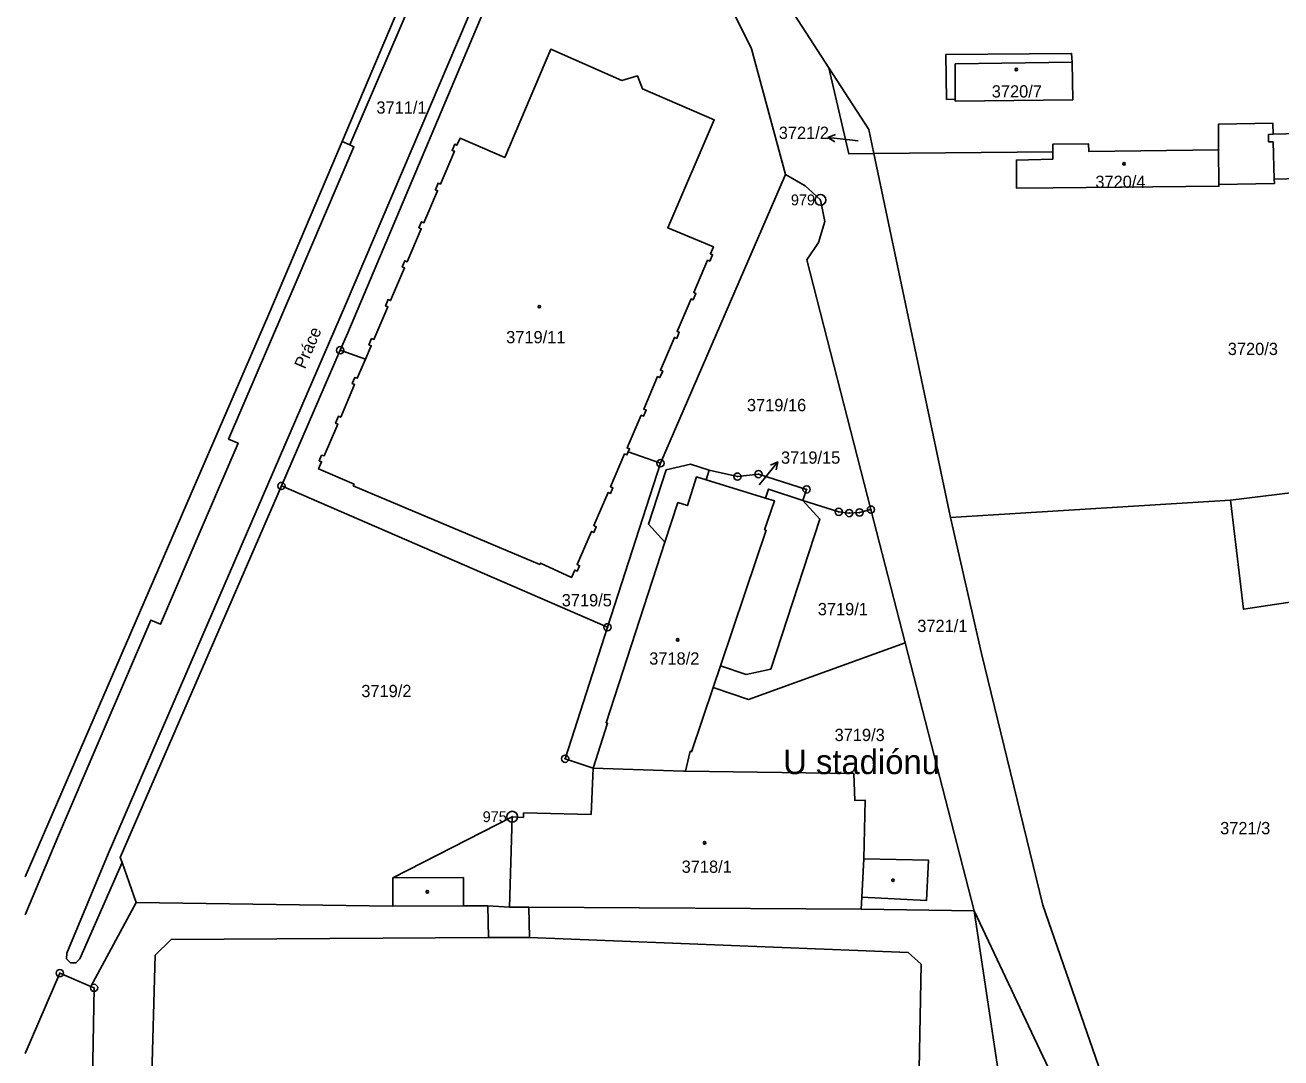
# Model space of a CAD drawing. Extents: x -747779 to -747197, y -965543 to -964919.
# Drawn here: x -747775.5 to -747601.4, y -965381 to -965237.8 of the extents above; entities that cross this region are included whole.
import ezdxf

# ---------------------------------------------------------------- set-up
doc = ezdxf.new("R2010")
doc.units = 0
for name, color, linetype in [('Hranice parcel', 7, 'Continuous'), ('Parcelní čísla', 7, 'Continuous'), ('Pop  PČ popisy', 7, 'Continuous'), ('Vnitřní kresba', 7, 'Continuous'), ('Značky bodu BP', 7, 'Continuous'), ('Značky budov', 7, 'Continuous')]:
    doc.layers.add(name, color=color, linetype=linetype)

msp = doc.modelspace()

# ---------------------------------------------------------------- linework, layer by layer
at = {"layer": 'Hranice parcel'}
for p, q in [((-747681.26, -965217.18), (-747664.09, -965243.73)), ((-747657.85, -965255.61), (-747633.05, -965255.35)), ((-747657.85, -965255.61), (-747647.24, -965306.07)), ((-747687.45, -965298.55), (-747670.12, -965258.53)), ((-747731.85, -965282.88), (-747740, -965301.7)), ((-747731.85, -965282.88), (-747728.35, -965284.12)), ((-747691.91, -965296.97), (-747687.45, -965298.55)), ((-747694.79, -965321.29), (-747687.45, -965298.55)), ((-747694.79, -965321.29), (-747740, -965301.7)), ((-747653.53, -965323.44), (-747658.27, -965304.98)), ((-747643.98, -965360.59), (-747653.53, -965323.44)), ((-747760.15, -965359.47), (-747766.44, -965371.1)), ((-747724.54, -965359.98), (-747760.15, -965359.47)), ((-747643.98, -965360.59), (-747659.62, -965360.4)), ((-747625.57, -965399.47), (-747643.98, -965360.59))]:
    msp.add_line(p, q, dxfattribs=at)
for points in [[(-747656.73, -965070.94), (-747661.79, -965091.8), (-747695.94, -965170.11), (-747711.36, -965206.23), (-747731.59, -965253.94)], [(-747687.21, -965223.29), (-747695.62, -965214.69), (-747698.17, -965212.99), (-747701.29, -965213.25), (-747703.51, -965215.83), (-747730.8, -965280.44), (-747731.85, -965282.88)], [(-747687.21, -965223.29), (-747677.55, -965235.57), (-747674.82, -965241.09), (-747670.12, -965258.53)], [(-747728.35, -965284.12), (-747727.55, -965282.25), (-747727.87, -965282.11), (-747727.5, -965281.26), (-747727.17, -965281.38), (-747725.24, -965276.87), (-747725.56, -965276.73), (-747725.2, -965275.86), (-747724.87, -965275.99), (-747722.93, -965271.46), (-747723.25, -965271.32), (-747722.89, -965270.47), (-747722.56, -965270.6), (-747720.61, -965266.04), (-747720.94, -965265.9), (-747720.58, -965265.06), (-747720.25, -965265.2), (-747718.35, -965260.75), (-747718.65, -965260.62), (-747718.28, -965259.69), (-747717.95, -965259.83), (-747716.02, -965255.29), (-747716.33, -965255.16), (-747715.97, -965254.31), (-747715.67, -965254.44), (-747715.24, -965253.48), (-747709.04, -965256.13), (-747702.67, -965241.15), (-747692.8, -965245.46), (-747690.64, -965244.84), (-747689.96, -965246.61), (-747679.99, -965250.94), (-747686.45, -965265.9), (-747680.12, -965268.53), (-747680.53, -965269.5), (-747680.22, -965269.63), (-747680.61, -965270.52), (-747680.92, -965270.39), (-747682.84, -965274.88), (-747682.54, -965275.01), (-747682.91, -965275.87), (-747683.21, -965275.75), (-747685.15, -965280.26), (-747684.84, -965280.39), (-747685.2, -965281.23), (-747685.51, -965281.1), (-747687.45, -965285.64), (-747687.14, -965285.79), (-747687.53, -965286.67), (-747687.84, -965286.54), (-747689.76, -965291.04), (-747689.43, -965291.18), (-747689.8, -965292.02), (-747690.12, -965291.88), (-747692.07, -965296.43), (-747691.74, -965296.57), (-747691.91, -965296.97)], [(-747630.26, -965248.14), (-747646.59, -965248.32), (-747646.6, -965248.06), (-747647.79, -965248.1), (-747647.9, -965241.89), (-747630.46, -965241.71), (-747630.38, -965242.95), (-747630.26, -965248.14)], [(-747664.09, -965243.73), (-747658.55, -965252.29), (-747657.85, -965255.61)], [(-747657.85, -965255.61), (-747661.33, -965255.65), (-747664.09, -965243.73)], [(-747588.73, -965252.47), (-747588.55, -965259.42), (-747588.9, -965259.43), (-747588.92, -965258.62), (-747593.7, -965258.74), (-747593.7, -965258.94), (-747602.35, -965259.16), (-747602.34, -965259.76), (-747610.02, -965259.88), (-747610.02, -965260.13), (-747632.99, -965260.36), (-747638.07, -965260.41), (-747638.11, -965256.51), (-747633.04, -965256.38), (-747633.05, -965255.35)], [(-747633.05, -965255.35), (-747633.06, -965254.31), (-747628.09, -965254.26), (-747628.08, -965255.3), (-747610.07, -965255.11), (-747610.11, -965251.53), (-747602.55, -965251.41), (-747602.51, -965252.93), (-747593.78, -965252.7), (-747593.79, -965252.6), (-747588.97, -965252.48), (-747588.73, -965252.47)], [(-747731.59, -965253.94), (-747730.5, -965254.41), (-747729.94, -965254.65), (-747738.08, -965273.72), (-747747.33, -965295.19), (-747746, -965295.76), (-747750.84, -965307.06), (-747756.76, -965320.87), (-747758.1, -965320.29), (-747764.97, -965336.33), (-747771.05, -965350.51), (-747775.53, -965361.16)], [(-747731.59, -965253.94), (-747741.74, -965277.87), (-747775.53, -965355.9)], [(-747670.12, -965258.53), (-747667.4, -965260.06), (-747665.27, -965262.03), (-747664.68, -965265.03), (-747665.55, -965267.95), (-747667.17, -965270.35), (-747658.27, -965304.98)], [(-747691.91, -965296.97), (-747692.09, -965297.39), (-747692.42, -965297.25), (-747694.37, -965301.8), (-747694.04, -965301.96), (-747694.38, -965302.74), (-747694.72, -965302.6), (-747696.69, -965307.2), (-747696.36, -965307.35), (-747696.7, -965308.14), (-747697.03, -965308), (-747699, -965312.59), (-747698.67, -965312.75), (-747698.99, -965313.5), (-747699.33, -965313.36), (-747699.76, -965314.37), (-747704.08, -965312.38), (-747704.18, -965312.61), (-747730.03, -965301.67), (-747729.93, -965301.45), (-747734.85, -965299.33), (-747734.43, -965298.35), (-747734.76, -965298.21), (-747734.42, -965297.44), (-747734.09, -965297.54), (-747732.19, -965293.12), (-747732.49, -965292.99), (-747732.1, -965292.04), (-747731.78, -965292.16), (-747729.85, -965287.63), (-747730.18, -965287.49), (-747729.81, -965286.64), (-747729.48, -965286.77), (-747728.35, -965284.12)], [(-747647.24, -965306.07), (-747608.41, -965303.66), (-747606.63, -965318.79), (-747574.68, -965313.98), (-747576.1, -965299.7), (-747544.78, -965296.1)], [(-747680.69, -965299.51), (-747683.27, -965298.66), (-747686.68, -965299.46), (-747689.12, -965306.99), (-747686.83, -965309.48), (-747694.98, -965334.53), (-747694.78, -965334.59), (-747696.77, -965340.84)], [(-747667.69, -965303.7), (-747672.49, -965302.14), (-747672.88, -965303.37), (-747681.12, -965300.85), (-747680.69, -965299.51)], [(-747667.69, -965303.7), (-747667.19, -965302.18), (-747673.87, -965300.05), (-747676.78, -965300.4), (-747680.69, -965299.51)], [(-747740, -965301.7), (-747762.33, -965353.22), (-747762.09, -965353.91), (-747760.15, -965359.47)], [(-747680.15, -965329.64), (-747679.14, -965326.64), (-747675.58, -965327.82), (-747672.13, -965327.08), (-747665.35, -965306.3), (-747667.69, -965303.7)], [(-747658.27, -965304.98), (-747659.85, -965305.38), (-747661.28, -965305.46), (-747662.74, -965305.29), (-747667.69, -965303.7)], [(-747621.4, -965397.45), (-747634.43, -965359.81), (-747642.96, -965324.94), (-747647.24, -965306.07)], [(-747696.77, -965340.84), (-747700.67, -965339.52), (-747694.79, -965321.29)], [(-747680.15, -965329.64), (-747675.25, -965331.29), (-747653.53, -965323.44)], [(-747683.97, -965341.25), (-747683.34, -965338.49), (-747683.15, -965338.55), (-747680.15, -965329.64)], [(-747696.77, -965340.84), (-747697.07, -965347.24), (-747706.42, -965347.04), (-747706.46, -965347.65), (-747708, -965347.56), (-747724.55, -965356.02), (-747724.54, -965359.98)], [(-747683.97, -965341.25), (-747684.27, -965341.25), (-747696.77, -965340.84)], [(-747659.62, -965360.4), (-747659.54, -965358.73), (-747650.55, -965359.16), (-747650.31, -965353.58), (-747659.25, -965353.4), (-747659.09, -965345.25), (-747660.52, -965345.29), (-747660.62, -965341.59), (-747683.97, -965341.25)], [(-747659.62, -965360.4), (-747705.68, -965360.1), (-747708.38, -965360.1), (-747711.36, -965359.94), (-747714.74, -965359.94), (-747724.54, -965359.98)], [(-747775.53, -965380.41), (-747770.71, -965369.25), (-747766.44, -965371.1)], [(-747766.44, -965371.1), (-747765.97, -965371.3), (-747766.27, -965389.07), (-747767.04, -965390.85), (-747765.66, -965391.44), (-747766.85, -965394.19), (-747768.23, -965393.6), (-747771.71, -965401.67)]]:
    msp.add_lwpolyline(points, dxfattribs=at)
at = {"layer": 'Pop  PČ popisy'}
for p, q in [((-747664.23, -965253.38), (-747663.19, -965252.98)), ((-747661.25, -965253.69), (-747664.23, -965253.38)), ((-747664.23, -965253.38), (-747663.29, -965253.98)), ((-747660.06, -965253.82), (-747661.25, -965253.69)), ((-747673.07, -965300.7), (-747671.18, -965298.37)), ((-747671.18, -965298.37), (-747672.2, -965298.83)), ((-747671.18, -965298.37), (-747671.42, -965299.46)), ((-747673.75, -965301.55), (-747673.07, -965300.7))]:
    msp.add_line(p, q, dxfattribs=at)
at = {"layer": 'Vnitřní kresba'}
for p, q in [((-747694.6, -965170.66), (-747730.5, -965254.41)), ((-747731.13, -965276.6), (-747704.39, -965213.92)), ((-747646.61, -965243.14), (-747630.38, -965242.95)), ((-747646.6, -965248.06), (-747646.61, -965243.14)), ((-747603.16, -965252.94), (-747602.51, -965252.93)), ((-747603.14, -965253.99), (-747603.16, -965252.94)), ((-747602.49, -965253.97), (-747603.14, -965253.99)), ((-747602.35, -965259.16), (-747602.49, -965253.97)), ((-747610.07, -965255.11), (-747610.02, -965259.88)), ((-747764.02, -965352.71), (-747731.13, -965276.6)), ((-747608.41, -965303.66), (-747576.1, -965299.7)), ((-747708.38, -965360.1), (-747708, -965347.56)), ((-747764.02, -965352.71), (-747769.76, -965366.5)), ((-747659.25, -965353.4), (-747659.54, -965358.73)), ((-747724.55, -965356.02), (-747714.75, -965355.98)), ((-747714.75, -965355.98), (-747714.74, -965359.94)), ((-747711.36, -965359.94), (-747711.31, -965364.32)), ((-747705.68, -965360.1), (-747705.59, -965364.33)), ((-747643.98, -965360.59), (-747637.7, -965402.11)), ((-747755.3, -965364.6), (-747757.51, -965366.75)), ((-747711.31, -965364.32), (-747755.3, -965364.6)), ((-747711.31, -965364.32), (-747705.59, -965364.33)), ((-747653.12, -965366.4), (-747705.59, -965364.33)), ((-747769.76, -965366.5), (-747769.79, -965367.27)), ((-747757.51, -965366.75), (-747758.58, -965407.41)), ((-747651.31, -965368.01), (-747653.12, -965366.4)), ((-747652.51, -965432.54), (-747651.31, -965368.01))]:
    msp.add_line(p, q, dxfattribs=at)
for points in [[(-747681.12, -965300.85), (-747682.44, -965300.45), (-747683.71, -965304.42), (-747685.04, -965303.99), (-747686.83, -965309.48)], [(-747679.14, -965326.64), (-747675.71, -965316.45), (-747672.81, -965307.84), (-747673.01, -965307.77), (-747671.65, -965303.74), (-747672.88, -965303.37)], [(-747769.79, -965367.27), (-747769.24, -965367.81), (-747768.49, -965367.83), (-747767.93, -965367.28), (-747762.09, -965353.91)]]:
    msp.add_lwpolyline(points, dxfattribs=at)
at = {"layer": 'Značky bodu BP'}
for centre, radius in [((-747665.27, -965262.03), 0.75), ((-747665.27, -965262.03), 0.03), ((-747731.85, -965282.88), 0.5), ((-747731.85, -965282.88), 0.0303), ((-747687.45, -965298.55), 0.5), ((-747687.45, -965298.55), 0.0303), ((-747676.78, -965300.4), 0.5), ((-747673.87, -965300.05), 0.5), ((-747740, -965301.7), 0.5), ((-747676.78, -965300.4), 0.0303), ((-747673.87, -965300.05), 0.0303), ((-747740, -965301.7), 0.0303), ((-747667.19, -965302.18), 0.5), ((-747667.19, -965302.18), 0.0303), ((-747662.74, -965305.29), 0.5), ((-747661.28, -965305.46), 0.5), ((-747659.85, -965305.38), 0.5), ((-747658.27, -965304.98), 0.5), ((-747658.27, -965304.98), 0.0303), ((-747662.74, -965305.29), 0.0303), ((-747661.28, -965305.46), 0.0303), ((-747659.85, -965305.38), 0.0303), ((-747694.79, -965321.29), 0.5), ((-747694.79, -965321.29), 0.0303), ((-747700.67, -965339.52), 0.5), ((-747700.67, -965339.52), 0.0303), ((-747708, -965347.56), 0.75), ((-747708, -965347.56), 0.03), ((-747770.71, -965369.25), 0.5), ((-747770.71, -965369.25), 0.0303), ((-747765.97, -965371.3), 0.5), ((-747765.97, -965371.3), 0.0303)]:
    msp.add_circle(centre, radius, dxfattribs=at)
at = {"layer": 'Značky budov'}
for centre in [(-747638.12, -965243.94), (-747623.18, -965257.03), (-747704.25, -965276.83), (-747685.06, -965323.03), (-747681.33, -965351.19), (-747655.21, -965356.37), (-747719.77, -965357.98)]:
    msp.add_circle(centre, 0.175, dxfattribs=at)

# ---------------------------------------------------------------- texts
at = {"layer": 'Parcelní čísla'}
for s, p in [('3720/7', (-747641.52, -965247.83)), ('3711/1', (-747726.83, -965250.07)), ('3721/2', (-747671.05, -965253.57)), ('3720/4', (-747627.16, -965260.37)), ('3719/11', (-747708.84, -965281.91)), ('3720/3', (-747608.8, -965283.54)), ('3719/16', (-747675.46, -965291.33)), ('3719/15', (-747670.74, -965298.61)), ('3719/5', (-747701.14, -965318.39)), ('3719/1', (-747665.64, -965319.62)), ('3721/1', (-747651.85, -965321.95)), ('3718/2', (-747689.01, -965326.47)), ('3719/2', (-747728.92, -965330.98)), ('3719/3', (-747663.31, -965337.07)), ('3721/3', (-747609.86, -965349.99)), ('3718/1', (-747684.51, -965355.34))]:
    msp.add_text(s, height=1.7, dxfattribs=at).set_placement(p)
at = {"layer": 'Pop  PČ popisy'}
msp.add_text('Práce', height=1.7, rotation=67, dxfattribs=at).set_placement((-747736.72, -965285.58))
msp.add_text('U stadiónu', height=3.4, dxfattribs=at).set_placement((-747670.44, -965341.65))
at = {"layer": 'Značky bodu BP'}
for s, p in [('979', (-747669.37, -965262.78)), ('975', (-747712.1, -965348.31))]:
    msp.add_text(s, height=1.5, dxfattribs=at).set_placement(p)

doc.saveas('drawing.dxf')
